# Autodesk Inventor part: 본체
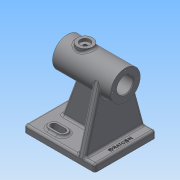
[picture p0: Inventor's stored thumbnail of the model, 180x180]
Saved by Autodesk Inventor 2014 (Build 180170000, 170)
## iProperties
Created: 2019-10
Part Number: 본체
Material: 일반
Document SubType Name: Modeling
Designer: NET
Density: 1 g/cm^3
Appearance: 기본값
Author: NET
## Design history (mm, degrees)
sketch "스케치1"
  geometry: L1 (-41, 0)-(41, 0); L2 (-41, 14.5)-(21, 14.5); L3 (21, 14.5)-(21, 11.5); L4 (21, 11.5)-(41, 11.5); L5 (41, 11.5)-(41, 21); L6 (41, 21)-(-41, 21); L7 (-41, 21)-(-41, 14.5); 2 further points
  constraints: 14 end point, 5 parallel, 2 point on line, 1 coincident, 1 horizontal, 1 midpoint, 1 perpendicular
  dimensions: "d0" = 82 distance of L1.start L1.end; "d1" = 23 diameter of L4 L1; "d2" = 29 diameter of L2 L1; "d3" = 42 diameter of L6 L1; "d4" = 62 distance of L2.start L2.end
revolve "회전1" sketch "스케치1" stored, may be unused: angle "d5" = 90 deg
node "작업 평면1"
sketch "스케치2"
  geometry: L1 (41, -21)-(41, 21) reference; L2 (-59, 43)-(41, 43); L3 (41, 43)-(41, -43); L4 (41, -43)-(-59, -43); L5 (-59, -43)-(-59, 43); 2 further points
  constraints: 8 end point, 2 parallel, 1 collinear, 1 horizontal, 1 horizontal alignment, 1 midpoint, 1 perpendicular
  dimensions: "d7" = 86 distance of L2.end L3.end; "d8" = 100 distance of L2.start L2.end
extrude "돌출1" join sketch "스케치2" distance "d9" = 10; taper "d10" = 0 deg
node "작업 평면2"
fillet "모깎기6" dims "d36" = 3
fillet "모깎기7" dims "d37" = 3
sketch "스케치4"
  geometry: L1 (-59, 43)-(-59, -43) reference; L2 (-33, 27)-(-21, 27); L3 (-33, 20)-(-21, 20); L4 (-21, 34)-(-33, 34); A1 r 7 centre (-33, 27) between (-33, 34) and (-33, 20); A2 r 7 centre (-21, 27) between (-21, 20) and (-21, 34); 2 further points
  constraints: 8 end point, 4 point on circle, 4 tangent, 2 centre point, 1 horizontal, 1 midpoint, 1 parallel
  dimensions: "d14" = 26 distance from line of L1 L2.start; "d15" = 12 distance of L2.start L2.end; "d16" = 7 radius of A1; "d17" = 27 distance from line of point (0, 0) L2
extrude "돌출3" join sketch "스케치4" distance "d18" = 3; taper "d19" = 0 deg
sketch "스케치5"
  geometry: L1 (-33, 20)-(-21, 20) reference; L2 (-33, 27)-(-21, 27); L3 (-33, 22.5)-(-21, 22.5); L4 (-21, 31.5)-(-33, 31.5); A1 r 7 centre (-21, 27) between (-21, 20) and (-21, 34) reference; A2 r 7 centre (-33, 27) between (-33, 34) and (-33, 20) reference; A3 r 4.5 centre (-33, 27) between (-33, 31.5) and (-33, 22.5); A4 r 4.5 centre (-21, 27) between (-21, 22.5) and (-21, 31.5); 2 further points
  constraints: 8 end point, 4 point on circle, 4 tangent, 2 centre point, 2 parallel, 1 midpoint
  dimensions: "d20" = 4.5 radius of A4
extrude "돌출4" cut sketch "스케치5" stored distance "d21" = 3; taper "d22" = 0 deg
fillet "모깎기1" dims "d23" = 3
sketch "스케치7"
  geometry: L1 (76, -40)-(76, 40) reference; L2 (79, 43)-(86, 43) reference; L3 (86, 43)-(86, -43) reference; L4 (86, -43)-(79, -43) reference; L5 (78.217, 42.896)-(-5.48, 20.272); L6 (78.217, -42.896)-(-5.48, -20.272); C1 r 11.5 at (0, 0) reference; A1 r 3 centre (79, 40) between (79, 43) and (76, 40) reference; A2 r 3 centre (79, -40) between (76, -40) and (79, -43) reference; A3 r 21 centre (0, 0) between (-5.48, 20.272) and (-5.48, -20.272) reference; 1 further point
  constraints: 4 end point, 4 point on circle, 4 tangent
extrude "돌출5" join sketch "스케치7" distance "d38" = 10; taper "d39" = 0 deg
fillet "모깎기8" dims "d40" = 3
fillet "모깎기9" dims "d41" = 3
sketch "스케치8"
  geometry: L1 (41, 21)-(41, 14.5) reference; L2 (41, 14.5)-(-21, 14.5) reference; L3 (-21, 14.5)-(-21, 11.5) reference; L4 (-21, 11.5)-(-41, 11.5) reference; L5 (-41, 11.5)-(-41, 21) reference; L6 (-41, 21)-(41, 21) reference; L7 (41, -14.5)-(41, -21) reference; L8 (41, -21)-(-16, -21) reference; L9 (-16, -21)-(-16, -76) reference; L10 (-16, -76)-(56, -76) reference; L11 (59, -79)-(59, -86) reference; L12 (59, -86)-(-41, -86) reference; L13 (-41, -86)-(-41, -79) reference; L14 (-38, -76)-(-29, -76) reference; L15 (-26, -73)-(-26, -21) reference; L16 (-26, -21)-(-41, -21) reference; L17 (-41, -21)-(-41, -11.5) reference; L18 (-41, -11.5)-(-21, -11.5) reference; L19 (-21, -11.5)-(-21, -14.5) reference; L20 (-21, -14.5)-(41, -14.5) reference; L21 (44, -76)-(24.357, -22.031); A1 r 3 centre (56, -79) between (59, -79) and (56, -76) reference; A2 r 3 centre (-38, -79) between (-38, -76) and (-41, -79) reference; A3 r 3 centre (-29, -73) between (-29, -76) and (-26, -73) reference; 1 further point
  constraints: 2 end point, 1 point on line
  dimensions: "d42" = 15 distance from line of L11 L21.start; "d43" = 70 deg angle of L10 L21
feature "리브2" sketch "스케치8" dims "d44" = 1, "d45" = 10, "d46" = 0, "d47" = 0, "d48" = 1, "d49" = 1
fillet "모깎기10" dims "d50" = 3
fillet "모깎기11" dims "d51" = 3
sketch "스케치9"
  geometry: C1 r 11.5 at (0, 0) reference; 1 further point
  constraints: 1 vertical alignment
  dimensions: "d52" = 18 distance of C1.centre point (0, 18)
hole "구멍1" sketch "스케치9" at (0, 18) diameter "d53" = 2.459; stored, may be unused: countersink angle "d57" = 90 deg, drill point angle "d59" = 118 deg; dims "d54" = 8, "d55" = 4, "d56" = 2, "d58" = 10
chamfer "모따기1" distance "d63" = 1; stored, may be unused: second distance "d64" = 2, angle "d65" = 45 deg
chamfer "모따기2" distance "d66" = 1; stored, may be unused: second distance "d67" = 2, angle "d68" = 45 deg
node "작업 평면3"
sketch "스케치10"
  geometry: L1 (-41, -21)-(-41, 21) reference; L2 (41, -21)-(41, 21) reference; C1 r 11 at (-16, 0); 2 further points
  constraints: 1 centre point, 1 horizontal alignment, 1 midpoint
  dimensions: "d70" = 22 diameter of C1; "d71" = 25 distance from line of C1.centre L1
extrude "돌출6" join sketch "스케치10" stored distance "d72" = 10; taper "d73" = 0 deg
sketch "스케치11"
  geometry: C1 r 11 at (0, 0) reference; C2 r 7 at (0, 0); 1 further point
  constraints: 1 centre point, 1 coincident
  dimensions: "d74" = 14 diameter of C2
extrude "돌출7" cut sketch "스케치11" distance "d75" = 4; taper "d76" = 0 deg
sketch "스케치12"
  geometry: C1 r 7 at (0, 0) reference; 2 further points
  constraints: 1 coincident
hole "구멍2" sketch "스케치12" at (0, 0) diameter "d77" = 4.917; stored, may be unused: countersink angle "d81" = 90 deg, drill point angle "d83" = 118 deg; dims "d78" = 8, "d79" = 4, "d80" = 2, "d82" = 10
fillet "모깎기12" dims "d84" = 3
sketch "스케치13"
  geometry: L1 (41, -40)-(41, 40) reference; 2 further points
  constraints: 1 horizontal alignment, 1 other
  dimensions: "d85" = 7 distance from line of point (34, 0) L1
feature "엠보싱1" sketch "스케치13" dims "d0" = 82, "d1" = 23, "d2" = 29, "d3" = 42, "d4" = 62, "d86" = 0.5, "d87" = 0
node "솔리드1"
mirror "대칭1"
pattern_circular "원형 패턴1" dims angle "d61" = 360 deg
mirror "대칭2"
node "절단 모서리 투영3"
node "절단 모서리 투영4"
other parameters: "d6" = -86, "d11" = -15, "d69" = 24
